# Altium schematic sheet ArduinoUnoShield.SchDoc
size A4
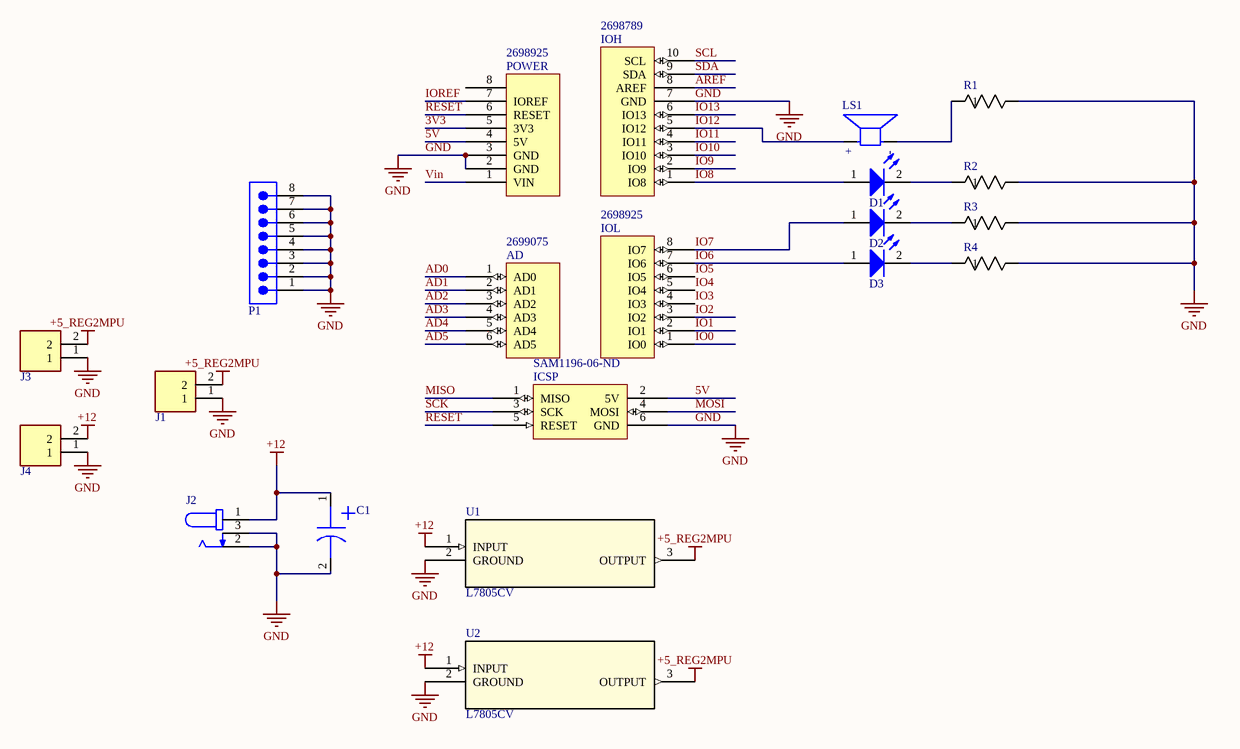
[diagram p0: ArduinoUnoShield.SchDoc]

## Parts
AD  Supplier Part Number 4: 2699075  [Header 6x1 8.5mm]  (hidden comment: AD)
C1  ESK475M035AC3AA  [CAP THT ELECTROLYTIC]  (value not drawn)
D1  Blue, 3.2V, 40°  [LED THROUGH HOLE]  (value not drawn)
D2  Blue, 3.2V, 40°  [LED THROUGH HOLE]  (value not drawn)
D3  Blue, 3.2V, 40°  [LED THROUGH HOLE]  (value not drawn)
ICSP  Supplier Part Number 5: SAM1196-06-ND  [ICSP]  (hidden comment: ICSP)
IOH  Supplier Part Number 3: 2698789  [Header 10x1 8.5mm]  (hidden comment: IOH)
IOL  Supplier Part Number 4: 2698925  [Header 8x1 8.5mm]  (hidden comment: IOL)
J1  282836-2  [TE_282836-2]  (value not drawn)
J2  DCJ200-10-A-XX-K_REVA  [DC POWER JACK]  (value not drawn)
J3  282836-2  [TE_282836-2]  (value not drawn)
J4  282836-2  [TE_282836-2]  (value not drawn)
LS1  AT-1224-TWT-5V-2-R  [BUZZER]  (value not drawn)
P1  61300811121  [8 PIN HEADER]  (value not drawn)
POWER  Supplier Part Number 4: 2698925  [Header 8x1 8.5mm]  (hidden comment: POWER_UNO)
R1  RNMF14FTC200R  [RESISTOR THROUGH HOLE]  (value not drawn)
R2  RNMF14FTC200R  [RESISTOR THROUGH HOLE]  (value not drawn)
R3  RNMF14FTC200R  [RESISTOR THROUGH HOLE]  (value not drawn)
R4  RNMF14FTC200R  [RESISTOR THROUGH HOLE]  (value not drawn)
U1  L7805CV  [7805 REG]
U2  L7805CV  [7805 REG]

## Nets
+5_REG2MPU: J1.2 J3.2 U1.3(OUTPUT) U2.3(OUTPUT)
+12: C1.1 J2.1 J4.2 U1.1(INPUT) U2.1(INPUT)
GND: C1.2 ICSP.6(GND) IOH.7(GND) J1.1 J2.2 J2.3 J3.1 J4.1 P1.1 P1.2 P1.3 P1.4 P1.5 P1.6 P1.7 P1.8 POWER.2(GND) POWER.3(GND) R1.2 R2.2 R3.2 R4.2 U1.2(GROUND) U2.2(GROUND)
3V3: POWER.5(3V3)
5V: ICSP.2(5V) POWER.4(5V)
AD0: AD.1(AD0)
AD1: AD.2(AD1)
AD2: AD.3(AD2)
AD3: AD.4(AD3)
AD4: AD.5(AD4)
AD5: AD.6(AD5)
AREF: IOH.8(AREF)
IO0: IOL.1(IO0)
IO1: IOL.2(IO1)
IO2: IOL.3(IO2)
IO3: IOL.4(IO3)
IO4: IOL.5(IO4)
IO5: IOL.6(IO5)
IO6: D3.1(A) IOL.7(IO6)
IO7: D2.1(A) IOL.8(IO7)
IO8: D1.1(A) IOH.1(IO8)
IO9: IOH.2(IO9)
IO10: IOH.3(IO10)
IO11: IOH.4(IO11)
IO12: IOH.5(IO12) LS1.P
IO13: IOH.6(IO13)
IOREF: POWER.7(IOREF)
MISO: ICSP.1(MISO)
MOSI: ICSP.4(MOSI)
RESET: ICSP.5(RESET) POWER.6(RESET)
SCK: ICSP.3(SCK)
SCL: IOH.10(SCL)
SDA: IOH.9(SDA)
Vin: POWER.1(VIN)
NetD1_2: D1.2(K) R2.1
NetD2_2: D2.2(K) R3.1
NetD3_2: D3.2(K) R4.1
NetLS1_N: LS1.N R1.1

Not connected (* = marked no-connect by the designer): POWER 8

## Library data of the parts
C1 = ESK475M035AC3AA: CAP ALUM 4.7UF 20% 35V RADIAL TH; Value: 4.7 µF 35 V Aluminum Electrolytic Capacitors Radial, Can 2000 Hrs @ 85°C
D1-D3 = 151051BS04000: WL-TMRC Mono-color Round Color, THT, D5.9 x H8.7mm, Blue, 3.2V, 40°; Manufacturer: Wurth Elektronik; Case/Size Code: 5mm; Chip Technology: GaN; Dominant Wavelength: 470nm; Luminous Intensity: 500mcd; Peak Wavelength: 465nm; Value: LED GREEN DIFFUSED 3MM ROUND T/H
J1 J3 J4 = 282836-2: Terminal Block Connector Wire Receptacle 2 5 mm 30-16 AWG Green 13.5 A 300 V ¦ TE Connectivity 282836-2
J2 = DCJ200-10-A-XX-K_REVA: Power Barrel Connector Jack 2.05mm ID (0.081), 5.50mm OD (0.217) Through Hole, Right Angle; MF: Global Connector Technology; MP: DCJ200-10-A-K1-K
LS1 = AT-1224-TWT-5V-2-R: Buzzers Transducer, Externally Driven Magnetic 5 V 50mA 2.4kHz 87dB @ 5V, 10cm Through Hole PC Pins; Value: BUZZER MAGNETIC 5V 12MM TH
P1 = 61300811121: WR-PHD Pin Header, THT, Vertical, pitch 2.54mm, 1 Row, 8P; Manufacturer: Wurth Elektronik; Contact Resistance: 20mOhm; Rated Current: 3A; Working Voltage: 250V; Withstanding Voltage: 500V
R1-R4 = RNMF14FTC200R: 200 Ohms ±1% 0.25W, 1/4W Through Hole Resistor Axial Flame Retardant Coating, Safety Metal Film; Mfr_Name: Stackpole International; Value: RES 200 OHM 1% 1/4W AXIAL
U1 U2 = L7805CV: Linear Voltage Regulator IC Positive Fixed 1 Output 1.5A TO-220; Mfr_Name: STMicroelectronics; Value: IC REG LINEAR 5V 1.5A TO220AB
